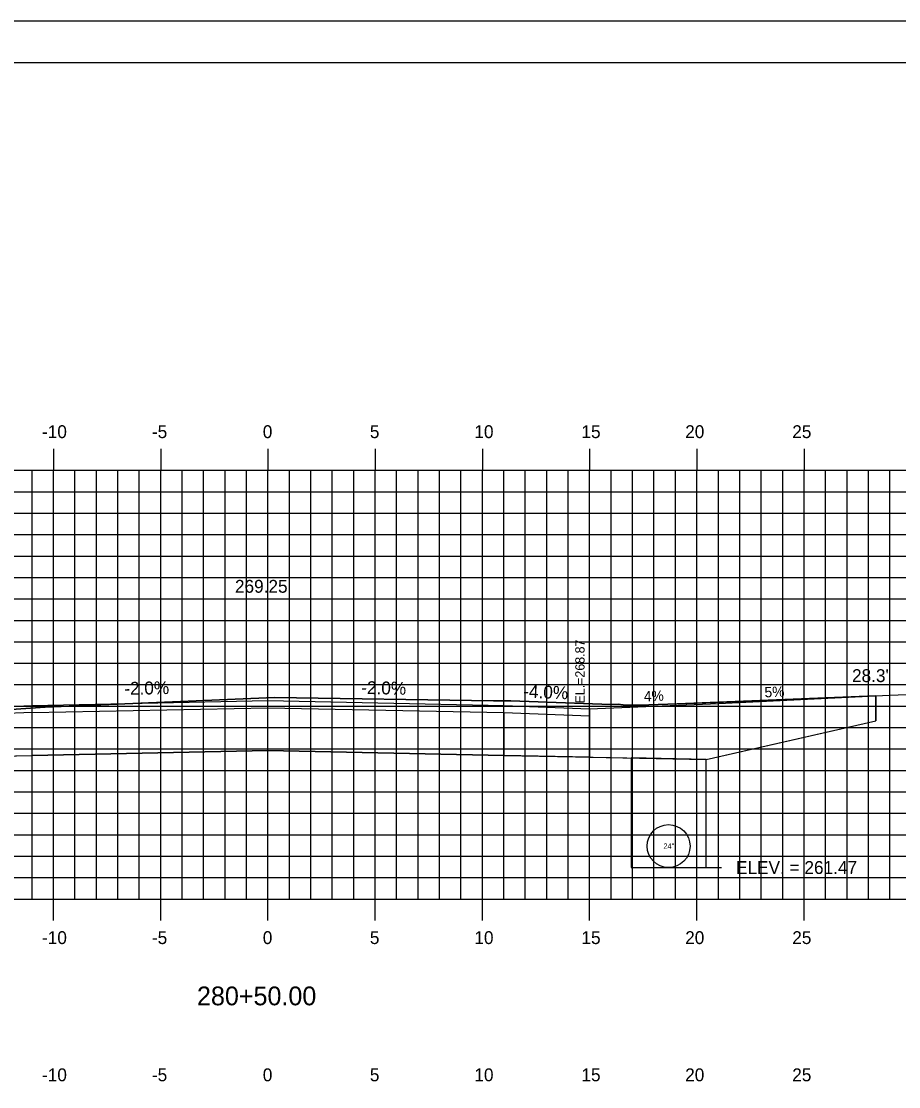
# Model space of a CAD drawing. Extents: x 855121 to 855291, y 366268 to 366378.
# Drawn here: x 855192.94 to 855233.85, y 366328.48 to 366378.18 of the extents above; entities that cross this region are included whole.
import ezdxf

# ---------------------------------------------------------------- set-up
doc = ezdxf.new("R2010")
doc.units = 0
for name, color, linetype in [('ANNOTATION', 7, 'Continuous'), ('BORDER', 7, 'Continuous'), ('D_Roadway_Centerline', 7, 'Continuous'), ('D_Roadway_Centerline_Text', 7, 'Continuous'), ('D_Roadway_Drive_Gravel_RT', 7, 'Continuous'), ('D_Roadway_Drive_SubGrade', 7, 'Continuous'), ('D_Roadway_Edge_Shoulder', 7, 'Continuous'), ('D_Roadway_SubGrade', 7, 'Continuous'), ('D_Text_Standard', 7, 'Continuous'), ('H_V ANNOTATION', 7, 'Continuous'), ('JUNK COM EXC', 7, 'Continuous'), ('junk strct exc', 7, 'Continuous'), ('MAJOR', 7, 'Continuous'), ('MINOR', 7, 'Continuous'), ('PDRAIN', 7, 'Continuous'), ('PLOT BOUNDARY', 7, 'Continuous'), ('S_Roadway_Centerline', 7, 'Continuous')]:
    doc.layers.add(name, color=color, linetype=linetype)

msp = doc.modelspace()

# ---------------------------------------------------------------- linework, layer by layer
at = {"layer": 'BORDER'}
msp.add_line((855289.442, 366376.236), (855129.442, 366376.236), dxfattribs=at)
at = {"layer": 'D_Roadway_Centerline'}
msp.add_lwpolyline([(855193.442, 366346.271), (855204.442, 366346.491), (855215.442, 366346.271)], dxfattribs=at)
at = {"layer": 'D_Roadway_Drive_Gravel_RT'}
for p, q in [((855225.442, 366346.35), (855232.79, 366346.718)), ((855219.442, 366346.11), (855225.442, 366346.35)), ((855225.442, 366346.35), (855225.442, 366346.35))]:
    msp.add_line(p, q, dxfattribs=at)
at = {"layer": 'D_Roadway_Drive_SubGrade'}
for p, q in [((855232.79, 366346.718), (855232.79, 366345.551)), ((855224.874, 366343.749), (855232.79, 366345.55)), ((855219.441, 366343.858), (855224.874, 366343.749))]:
    msp.add_line(p, q, dxfattribs=at)
at = {"layer": 'D_Roadway_Edge_Shoulder'}
msp.add_line((855219.442, 366346.11), (855219.441, 366345.778), dxfattribs=at)
msp.add_lwpolyline([(855185.587, 366345.957), (855193.442, 366346.271), (855204.442, 366346.491), (855215.442, 366346.271), (855219.442, 366346.11)], dxfattribs=at)
at = {"layer": 'D_Roadway_SubGrade'}
for points in [[(855193.442, 366343.938), (855193.442, 366345.938), (855204.442, 366346.158), (855215.442, 366345.938), (855215.442, 366343.938), (855204.442, 366344.158)], [(855193.442, 366345.938), (855185.587, 366345.623), (855185.587, 366343.78), (855193.442, 366343.938)], [(855215.442, 366345.938), (855219.441, 366345.778), (855219.441, 366343.858), (855215.442, 366343.938)]]:
    msp.add_lwpolyline(points, close=True, dxfattribs=at)
at = {"layer": 'D_Text_Standard'}
msp.add_lwpolyline([(855224.874, 366338.706), (855224.907, 366338.706), (855225.587, 366338.706)], dxfattribs=at)
at = {"layer": 'JUNK COM EXC'}
msp.add_lwpolyline([(855184.587, 366343.75), (855193.442, 366343.938), (855204.442, 366344.158), (855215.442, 366343.938), (855220.442, 366343.838), (855224.874, 366343.749), (855228.832, 366344.649), (855232.79, 366345.551), (855232.79, 366346.718), (855223.526, 366346.346), (855221.747, 366346.285), (855220.997, 366346.289), (855220.775, 366346.323), (855220.442, 366346.316), (855220.431, 366346.316), (855215.768, 366346.474), (855214.965, 366346.488), (855204.747, 366346.643), (855199.995, 366346.43), (855194.05, 366346.181), (855189.07, 366345.851)], dxfattribs=at)
at = {"layer": 'junk strct exc'}
msp.add_lwpolyline([(855221.374, 366343.819), (855221.374, 366338.706), (855224.874, 366338.706), (855224.874, 366343.749)], close=True, dxfattribs=at)
at = {"layer": 'MAJOR'}
for p, q in [((855194.442, 366358.238), (855194.442, 366357.236)), ((855199.442, 366358.238), (855199.442, 366357.236)), ((855204.442, 366358.238), (855204.442, 366357.236)), ((855209.442, 366358.238), (855209.442, 366357.236)), ((855214.442, 366358.238), (855214.442, 366357.236)), ((855219.442, 366358.238), (855219.442, 366357.236)), ((855224.442, 366358.238), (855224.442, 366357.236)), ((855229.442, 366358.238), (855229.442, 366357.236)), ((855134.442, 366357.236), (855274.442, 366357.236)), ((855134.442, 366357.236), (855274.442, 366357.236)), ((855194.442, 366337.236), (855194.442, 366357.236)), ((855199.442, 366337.236), (855199.442, 366357.236)), ((855204.442, 366337.236), (855204.442, 366357.236)), ((855209.442, 366337.236), (855209.442, 366357.236)), ((855214.442, 366337.236), (855214.442, 366357.236)), ((855219.442, 366337.236), (855219.442, 366357.236)), ((855224.442, 366337.236), (855224.442, 366357.236)), ((855229.442, 366337.236), (855229.442, 366357.236)), ((855134.442, 366352.236), (855274.442, 366352.236)), ((855134.442, 366347.236), (855274.442, 366347.236)), ((855134.442, 366342.236), (855274.442, 366342.236)), ((855134.442, 366337.236), (855274.442, 366337.236)), ((855134.442, 366337.236), (855274.442, 366337.236)), ((855194.442, 366336.234), (855194.442, 366337.236)), ((855199.442, 366336.234), (855199.442, 366337.236)), ((855204.442, 366336.234), (855204.442, 366337.236)), ((855209.442, 366336.234), (855209.442, 366337.236)), ((855214.442, 366336.234), (855214.442, 366337.236)), ((855219.442, 366336.234), (855219.442, 366337.236)), ((855224.442, 366336.234), (855224.442, 366337.236)), ((855229.442, 366336.234), (855229.442, 366337.236))]:
    msp.add_line(p, q, dxfattribs=at)
at = {"layer": 'MINOR'}
for p, q in [((855193.442, 366337.236), (855193.442, 366357.236)), ((855195.442, 366337.236), (855195.442, 366357.236)), ((855196.442, 366337.236), (855196.442, 366357.236)), ((855197.442, 366337.236), (855197.442, 366357.236)), ((855198.442, 366337.236), (855198.442, 366357.236)), ((855200.442, 366337.236), (855200.442, 366357.236)), ((855201.442, 366337.236), (855201.442, 366357.236)), ((855202.442, 366337.236), (855202.442, 366357.236)), ((855203.442, 366337.236), (855203.442, 366357.236)), ((855205.442, 366337.236), (855205.442, 366357.236)), ((855206.442, 366337.236), (855206.442, 366357.236)), ((855207.442, 366337.236), (855207.442, 366357.236)), ((855208.442, 366337.236), (855208.442, 366357.236)), ((855210.442, 366337.236), (855210.442, 366357.236)), ((855211.442, 366337.236), (855211.442, 366357.236)), ((855212.442, 366337.236), (855212.442, 366357.236)), ((855213.442, 366337.236), (855213.442, 366357.236)), ((855215.442, 366337.236), (855215.442, 366357.236)), ((855216.442, 366337.236), (855216.442, 366357.236)), ((855217.442, 366337.236), (855217.442, 366357.236)), ((855218.442, 366337.236), (855218.442, 366357.236)), ((855220.442, 366337.236), (855220.442, 366357.236)), ((855221.442, 366337.236), (855221.442, 366357.236)), ((855222.442, 366337.236), (855222.442, 366357.236)), ((855223.442, 366337.236), (855223.442, 366357.236)), ((855225.442, 366337.236), (855225.442, 366357.236)), ((855226.442, 366337.236), (855226.442, 366357.236)), ((855227.442, 366337.236), (855227.442, 366357.236)), ((855228.442, 366337.236), (855228.442, 366357.236)), ((855230.442, 366337.236), (855230.442, 366357.236)), ((855231.442, 366337.236), (855231.442, 366357.236)), ((855232.442, 366337.236), (855232.442, 366357.236)), ((855233.442, 366337.236), (855233.442, 366357.236)), ((855134.442, 366356.236), (855274.442, 366356.236)), ((855134.442, 366355.236), (855274.442, 366355.236)), ((855134.442, 366354.236), (855274.442, 366354.236)), ((855134.442, 366353.236), (855274.442, 366353.236)), ((855134.442, 366351.236), (855274.442, 366351.236)), ((855134.442, 366350.236), (855274.442, 366350.236)), ((855134.442, 366349.236), (855274.442, 366349.236)), ((855134.442, 366348.236), (855274.442, 366348.236)), ((855134.442, 366346.236), (855274.442, 366346.236)), ((855134.442, 366345.236), (855274.442, 366345.236)), ((855134.442, 366344.236), (855274.442, 366344.236)), ((855134.442, 366343.236), (855274.442, 366343.236)), ((855134.442, 366341.236), (855274.442, 366341.236)), ((855134.442, 366340.236), (855274.442, 366340.236)), ((855134.442, 366339.236), (855274.442, 366339.236)), ((855134.442, 366338.236), (855274.442, 366338.236))]:
    msp.add_line(p, q, dxfattribs=at)
at = {"layer": 'PDRAIN'}
msp.add_lwpolyline([(855221.374, 366343.819), (855221.374, 366338.706), (855224.874, 366338.706), (855224.874, 366343.749)], dxfattribs=at)
msp.add_circle((855223.124, 366339.706), 1, dxfattribs=at)
at = {"layer": 'PLOT BOUNDARY'}
msp.add_lwpolyline([(855121.349, 366268.177), (855291.349, 366268.177), (855291.349, 366378.177), (855121.349, 366378.177)], close=True, dxfattribs=at)
at = {"layer": 'S_Roadway_Centerline'}
msp.add_lwpolyline([(855144.138, 366345.236), (855154.981, 366345.612), (855167.747, 366345.731), (855178.089, 366345.883), (855179.388, 366345.897), (855182.154, 366346.026), (855184.948, 366346.054), (855186.531, 366346.008), (855186.852, 366345.93), (855188.684, 366345.832), (855189.07, 366345.851), (855194.05, 366346.181), (855199.995, 366346.43), (855204.747, 366346.643), (855214.965, 366346.488), (855215.768, 366346.474), (855220.431, 366346.316), (855220.775, 366346.323), (855220.997, 366346.289), (855221.747, 366346.285), (855225.306, 366346.406), (855236.796, 366346.885)], dxfattribs=at)

# ---------------------------------------------------------------- texts
at = {"layer": 'ANNOTATION'}
for s, rotation, p in [('-2.0%', 1.1458, (855197.745, 366346.757)), ('-2.0%', 358.8542, (855208.785, 366346.804)), ('-4.0%', 357.709, (855216.334, 366346.636))]:
    msp.add_text(s, height=0.6, rotation=rotation, dxfattribs=at).set_placement(p)
at = {"layer": 'D_Roadway_Centerline_Text'}
msp.add_text('269.25', height=0.6, dxfattribs=at).set_placement((855202.903, 366351.523))
at = {"layer": 'D_Roadway_Drive_Gravel_RT'}
for s, p in [('5%', (855227.605, 366346.642)), ('4%', (855221.978, 366346.452))]:
    msp.add_text(s, height=0.48, rotation=2.2906, dxfattribs=at).set_placement(p)
at = {"layer": 'D_Text_Standard'}
msp.add_text(' EL.=268.87', height=0.4335, rotation=90, dxfattribs=at).set_placement((855219.204, 366346.196))
for s, p in [("28.3'", (855231.675, 366347.357)), ('ELEV. = 261.47', (855226.267, 366338.406))]:
    msp.add_text(s, height=0.6, dxfattribs=at).set_placement(p)
at = {"layer": 'H_V ANNOTATION'}
for s, height, p in [('-10', 0.6, (855193.907, 366358.736)), ('-5', 0.6, (855199.032, 366358.736)), ('0', 0.6, (855204.201, 366358.736)), ('5', 0.6, (855209.193, 366358.736)), ('10', 0.6, (855214.067, 366358.736)), ('15', 0.6, (855219.059, 366358.736)), ('20', 0.6, (855223.896, 366358.736)), ('25', 0.6, (855228.888, 366358.736)), ('-10', 0.6, (855193.907, 366335.136)), ('-5', 0.6, (855199.032, 366335.136)), ('0', 0.6, (855204.201, 366335.136)), ('5', 0.6, (855209.193, 366335.136)), ('10', 0.6, (855214.067, 366335.136)), ('15', 0.6, (855219.059, 366335.136)), ('20', 0.6, (855223.896, 366335.136)), ('25', 0.6, (855228.888, 366335.136)), ('280+50.00', 0.875, (855201.133, 366332.28)), ('-10', 0.6, (855193.907, 366328.736)), ('-5', 0.6, (855199.032, 366328.736)), ('0', 0.6, (855204.201, 366328.736)), ('5', 0.6, (855209.193, 366328.736)), ('10', 0.6, (855214.067, 366328.736)), ('15', 0.6, (855219.059, 366328.736)), ('20', 0.6, (855223.896, 366328.736)), ('25', 0.6, (855228.888, 366328.736))]:
    msp.add_text(s, height=height, dxfattribs=at).set_placement(p)
at = {"layer": 'PDRAIN'}
msp.add_text('24"', height=0.25, dxfattribs=at).set_placement((855222.882, 366339.581))
at = {"layer": 'S_Roadway_Centerline'}
for s, p in [('C', (855204.742, 366346.643)), ('L', (855204.747, 366346.636))]:
    msp.add_text(s, height=0.0146, dxfattribs=at).set_placement(p)

doc.saveas('drawing.dxf')
